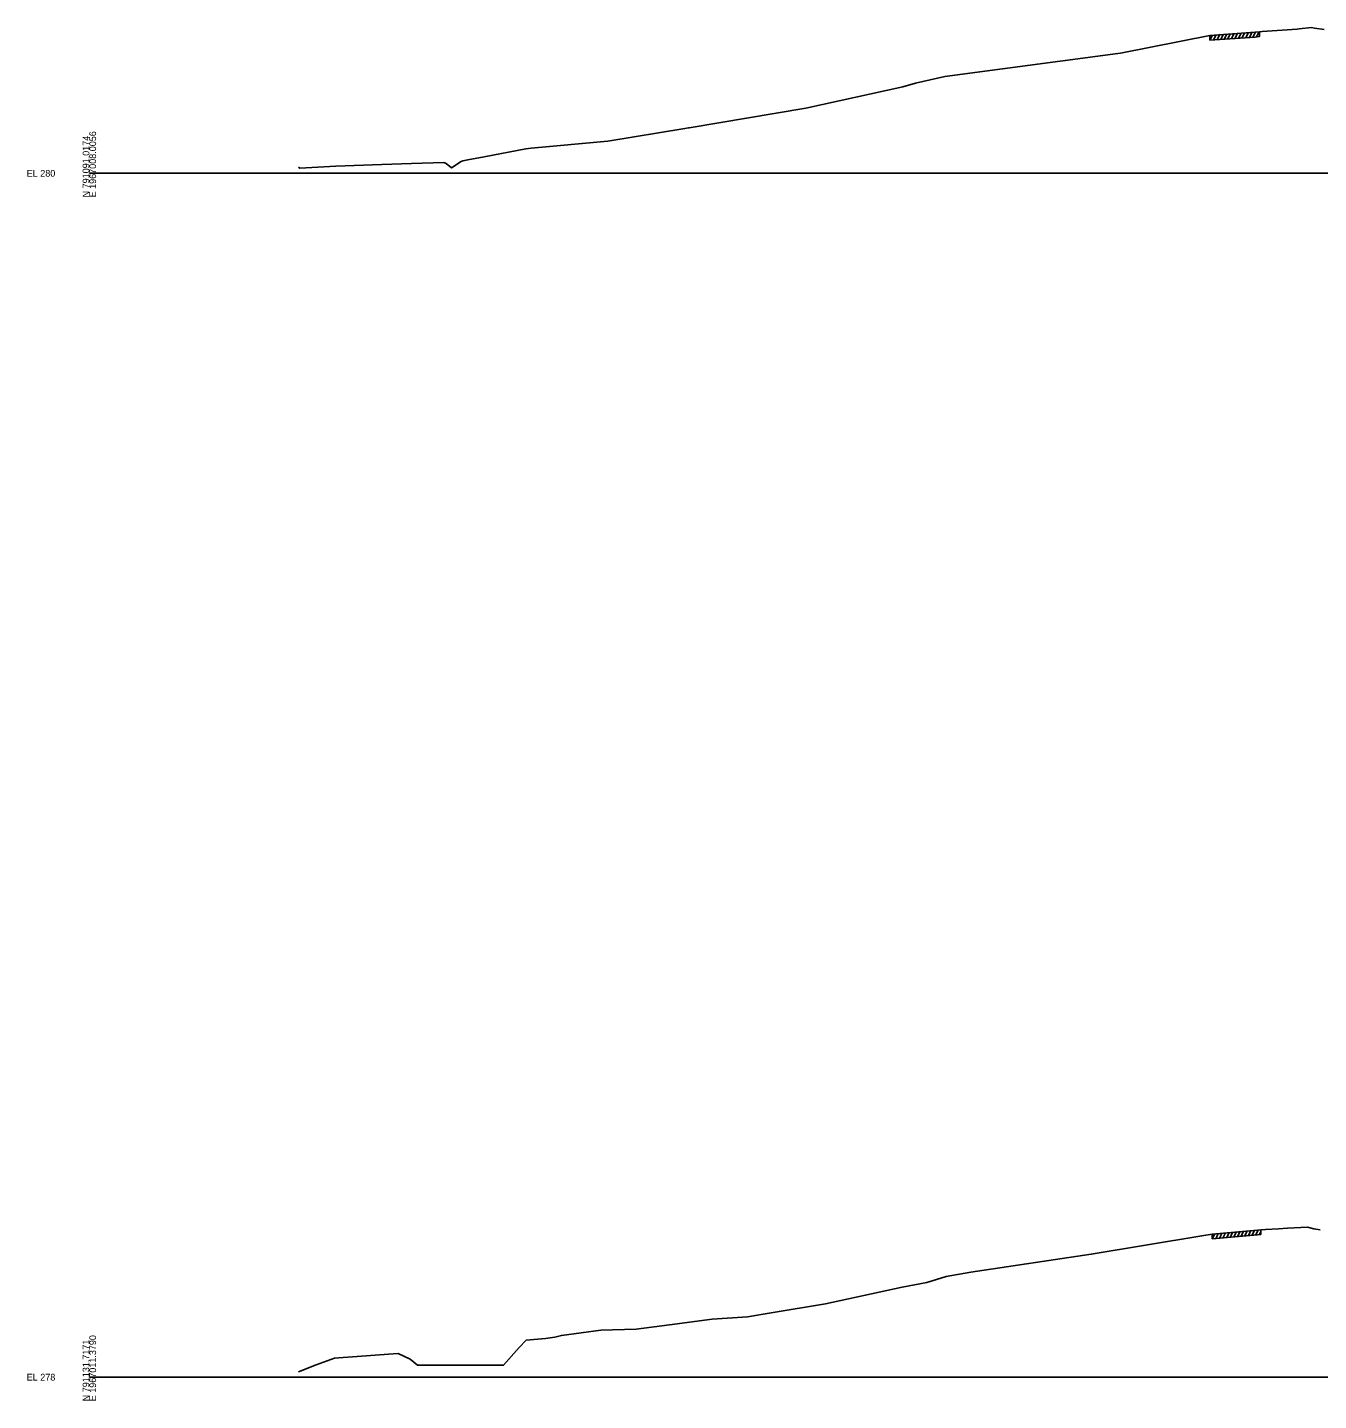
# Model space of a CAD drawing. Extents: x 1017 to 19997, y -1947 to 50737.
# Drawn here: x 17974 to 18510, y 8990 to 9561 of the extents above; entities that cross this region are included whole.
import ezdxf

# ---------------------------------------------------------------- set-up
doc = ezdxf.new("R2010")
doc.units = 0
for name, color, linetype in [('RD_GPK_XS_Cell', 7, 'Continuous'), ('RD_XS_ExGround', 7, 'Continuous'), ('RD_XS_ExPaveRet', 7, 'Continuous')]:
    doc.layers.add(name, color=color, linetype=linetype)

msp = doc.modelspace()

# ---------------------------------------------------------------- linework, layer by layer
at = {"layer": 'RD_GPK_XS_Cell'}
for p, q in [((18000, 9500), (18600, 9500)), ((18000, 9000), (18600, 9000))]:
    msp.add_line(p, q, dxfattribs=at)
at = {"layer": 'RD_XS_ExGround'}
for points in [[(18086.87, 9502.6), (18087.43, 9502.2), (18102.37, 9502.95), (18121.4, 9503.68), (18133.7, 9504.08), (18147.12, 9504.51), (18148.13, 9504.03), (18150.39, 9502.28), (18154.41, 9504.87), (18155.01, 9505.2), (18157.18, 9505.65), (18163.91, 9506.88), (18181.16, 9510.1), (18183.47, 9510.38), (18215.22, 9513.32), (18247.18, 9518.59), (18248.72, 9518.85), (18249.05, 9518.94), (18297.43, 9526.99), (18337.8, 9535.89), (18343.07, 9537.44), (18355.22, 9540.14), (18427.08, 9549.79), (18428.2, 9549.96), (18465.29, 9557.28), (18484.1, 9558.61), (18485.91, 9558.77), (18486.99, 9558.85), (18501.43, 9559.91), (18502.36, 9559.98), (18507.42, 9560.57), (18508.72, 9560.33), (18512.71, 9559.69)], [(18086.8, 9002.18), (18094.18, 9005.09), (18101.85, 9007.93), (18105.42, 9008.22), (18111.22, 9008.64), (18124.24, 9009.54), (18128.23, 9009.85), (18133.18, 9007.51), (18136.24, 9004.94), (18169.24, 9004.94), (18171.99, 9004.94), (18178.44, 9012.35), (18181.41, 9015.39), (18189.45, 9016.08), (18193.22, 9016.6), (18195.98, 9017.32), (18212.39, 9019.59), (18227.1, 9019.96), (18240.81, 9021.75), (18258.59, 9024.07), (18273.28, 9025.06), (18283.11, 9026.68), (18305.64, 9030.41), (18337.43, 9037.39), (18347.79, 9039.34), (18355.78, 9041.85), (18366.02, 9043.64), (18415.96, 9051.06), (18461.87, 9058.73), (18466.19, 9059.4), (18485.02, 9061.07), (18486.38, 9061.21), (18488.37, 9061.3), (18493.7, 9061.67), (18497.47, 9061.88), (18505.77, 9062.27), (18508.36, 9061.63), (18511.05, 9061.17)]]:
    msp.add_lwpolyline(points, dxfattribs=at)
at = {"layer": 'RD_XS_ExPaveRet'}
for p, q in [((18469.73, 9555.59), (18470.76, 9557.66)), ((18471.2, 9555.7), (18472.24, 9557.77)), ((18472.68, 9555.8), (18473.71, 9557.87)), ((18474.16, 9555.9), (18475.2, 9557.98)), ((18475.66, 9556.01), (18476.69, 9558.08)), ((18477.15, 9556.12), (18478.19, 9558.19)), ((18478.65, 9556.22), (18479.68, 9558.29)), ((18480.14, 9556.33), (18481.18, 9558.4)), ((18481.63, 9556.43), (18482.67, 9558.5)), ((18483.13, 9556.54), (18484.17, 9558.61)), ((18484.63, 9556.65), (18485.68, 9558.75)), ((18485.91, 9556.77), (18485.91, 9558.77)), ((18465.29, 9555.28), (18466.33, 9557.35)), ((18465.29, 9555.28), (18465.29, 9557.28)), ((18466.77, 9555.38), (18467.81, 9557.46)), ((18468.25, 9555.49), (18469.28, 9557.56)), ((18466.19, 9057.4), (18467.24, 9059.49)), ((18466.19, 9057.4), (18466.19, 9059.4)), ((18467.68, 9057.53), (18468.73, 9059.63)), ((18469.17, 9057.67), (18470.22, 9059.76)), ((18470.66, 9057.8), (18471.71, 9059.89)), ((18472.16, 9057.93), (18473.2, 9060.02)), ((18473.64, 9058.06), (18474.69, 9060.16)), ((18475.14, 9058.2), (18476.19, 9060.29)), ((18476.65, 9058.33), (18477.7, 9060.42)), ((18478.16, 9058.46), (18479.21, 9060.56)), ((18479.67, 9058.6), (18480.72, 9060.69)), ((18481.18, 9058.73), (18482.22, 9060.82)), ((18482.69, 9058.87), (18483.73, 9060.96)), ((18484.2, 9059), (18485.24, 9061.09)), ((18485.71, 9059.14), (18486.38, 9060.48)), ((18486.38, 9059.21), (18486.38, 9061.21))]:
    msp.add_line(p, q, dxfattribs=at)
for points in [[(18465.29, 9555.28), (18484.1, 9556.61), (18485.91, 9556.77)], [(18466.19, 9057.4), (18485.02, 9059.07), (18486.38, 9059.21)]]:
    msp.add_lwpolyline(points, dxfattribs=at)

# ---------------------------------------------------------------- texts
at = {"layer": 'RD_GPK_XS_Cell'}
for s, p in [('N 791091.0174', (18000, 9490)), ('E 1967008.0056', (18002.8, 9490)), ('E 1967011.3790', (18002.8, 8990)), ('N 791131.7171', (18000, 8990))]:
    msp.add_text(s, height=2.8, rotation=90, dxfattribs=at).set_placement(p)
for s, p in [('EL 280', (17974, 9498.6)), ('EL 278', (17974, 8998.6))]:
    msp.add_text(s, height=2.8, dxfattribs=at).set_placement(p)

doc.saveas('drawing.dxf')
